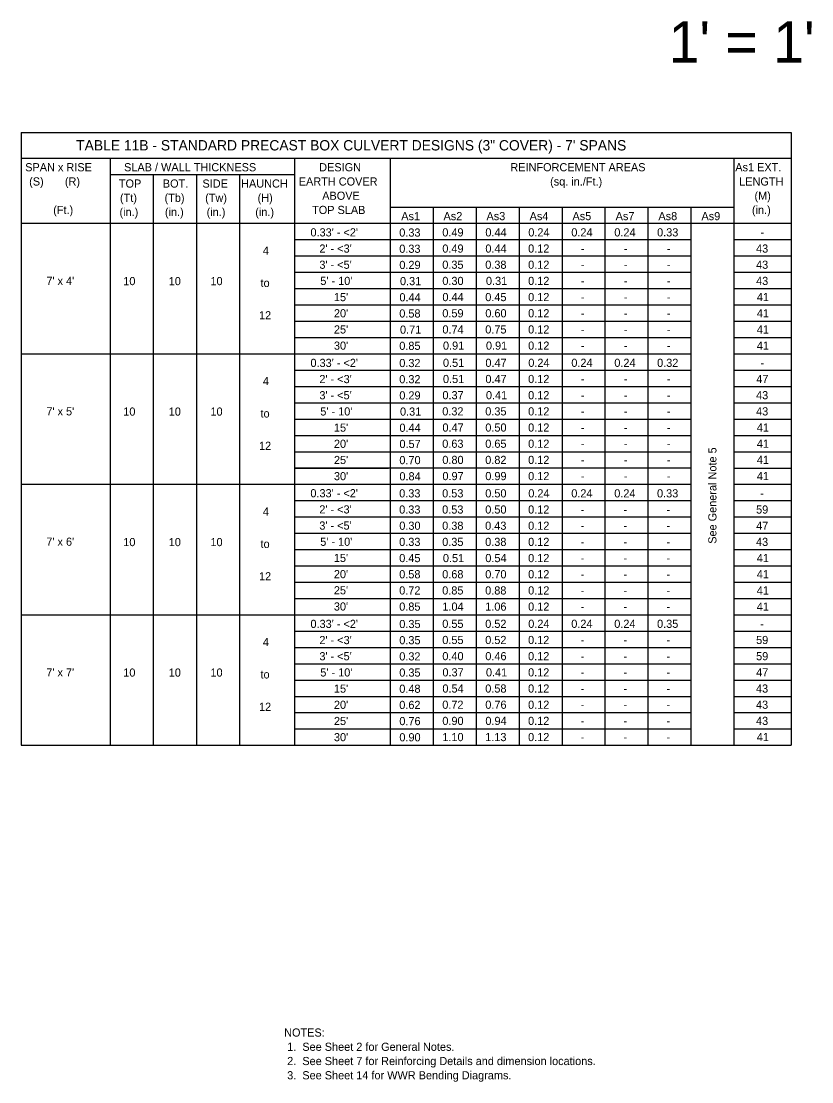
# Model space of a CAD drawing. Extents: x 10342.77 to 10344.98, y 76371.51 to 76372.62.
# Drawn here: x 10343.418 to 10344.028, y 76371.801 to 76372.621 of the extents above; entities that cross this region are included whole.
import ezdxf

# ---------------------------------------------------------------- set-up
doc = ezdxf.new("R2010")
doc.units = 0
doc.layers.add('AdhocPoint_dp', color=7, linetype='Continuous')
doc.layers.add('PlotBorder_dp', color=7, linetype='Continuous')

msp = doc.modelspace()

# ---------------------------------------------------------------- linework, layer by layer
at = {"layer": 'PlotBorder_dp'}
for p, q in [((10343.41763, 76372.53475), (10344.01237, 76372.53475)), ((10343.41763, 76372.53475), (10343.41763, 76372.06133)), ((10344.01237, 76372.53475), (10344.01237, 76372.06133)), ((10343.41763, 76372.51488), (10344.01237, 76372.51488)), ((10343.48627, 76372.51488), (10343.48627, 76372.06133)), ((10343.62871, 76372.51488), (10343.62871, 76372.06133)), ((10343.70259, 76372.51488), (10343.70259, 76372.06133)), ((10343.96818, 76372.51488), (10343.96818, 76372.06133)), ((10343.48627, 76372.50228), (10343.62871, 76372.50228)), ((10343.51963, 76372.50228), (10343.51963, 76372.06133)), ((10343.55299, 76372.50228), (10343.55299, 76372.06133)), ((10343.58635, 76372.50228), (10343.58635, 76372.06133)), ((10343.70259, 76372.47713), (10343.96818, 76372.47713)), ((10343.73579, 76372.47713), (10343.73579, 76372.06133)), ((10343.76899, 76372.47713), (10343.76899, 76372.06133)), ((10343.80219, 76372.47713), (10343.80219, 76372.06133)), ((10343.83539, 76372.47713), (10343.83539, 76372.06133)), ((10343.86858, 76372.47713), (10343.86858, 76372.06133)), ((10343.86858, 76372.47713), (10343.86858, 76372.06133)), ((10343.90178, 76372.47713), (10343.90178, 76372.06133)), ((10343.93498, 76372.47713), (10343.93498, 76372.06133)), ((10343.41763, 76372.46453), (10344.01237, 76372.46453)), ((10343.62871, 76372.45193), (10343.93498, 76372.45193)), ((10343.96818, 76372.45192), (10344.01237, 76372.45192)), ((10343.62871, 76372.43933), (10343.93498, 76372.43933)), ((10343.96818, 76372.43932), (10344.01237, 76372.43932)), ((10343.62871, 76372.42673), (10343.93498, 76372.42673)), ((10343.96818, 76372.42672), (10344.01237, 76372.42672)), ((10343.62871, 76372.41413), (10343.93498, 76372.41413)), ((10343.96818, 76372.41412), (10344.01237, 76372.41412)), ((10343.62871, 76372.40153), (10343.93498, 76372.40153)), ((10343.96818, 76372.40152), (10344.01237, 76372.40152)), ((10343.62871, 76372.38893), (10343.93498, 76372.38893)), ((10343.96818, 76372.38892), (10344.01237, 76372.38892)), ((10343.62871, 76372.37633), (10343.93498, 76372.37633)), ((10343.96818, 76372.37632), (10344.01237, 76372.37632)), ((10343.41763, 76372.36373), (10343.93498, 76372.36373)), ((10343.62931, 76372.36372), (10343.70148, 76372.36372)), ((10343.96818, 76372.36372), (10344.01237, 76372.36372)), ((10343.62871, 76372.35113), (10343.93498, 76372.35113)), ((10343.96818, 76372.35112), (10344.01237, 76372.35112)), ((10343.62871, 76372.33853), (10343.93498, 76372.33853)), ((10343.96818, 76372.33852), (10344.01237, 76372.33852)), ((10343.62871, 76372.32593), (10343.93498, 76372.32593)), ((10343.96818, 76372.32592), (10344.01237, 76372.32592)), ((10343.62871, 76372.31333), (10343.93498, 76372.31333)), ((10343.96818, 76372.31332), (10344.01237, 76372.31332)), ((10343.62871, 76372.30073), (10343.93498, 76372.30073)), ((10343.96818, 76372.30072), (10344.01237, 76372.30072)), ((10343.62871, 76372.28813), (10343.93498, 76372.28813)), ((10343.96818, 76372.28812), (10344.01237, 76372.28812)), ((10343.62871, 76372.27553), (10343.93498, 76372.27553)), ((10343.62931, 76372.27552), (10343.70148, 76372.27552)), ((10343.96818, 76372.27552), (10344.01237, 76372.27552)), ((10343.41763, 76372.26293), (10343.93498, 76372.26293)), ((10343.96818, 76372.26292), (10344.01237, 76372.26292)), ((10343.62871, 76372.25033), (10343.93498, 76372.25033)), ((10343.96818, 76372.25032), (10344.01237, 76372.25032)), ((10343.62871, 76372.23773), (10343.93498, 76372.23773)), ((10343.96818, 76372.23772), (10344.01237, 76372.23772)), ((10343.62871, 76372.22513), (10343.93498, 76372.22513)), ((10343.96818, 76372.22512), (10344.01237, 76372.22512)), ((10343.62871, 76372.21253), (10343.93498, 76372.21253)), ((10343.96818, 76372.21252), (10344.01237, 76372.21252)), ((10343.62871, 76372.19993), (10343.93498, 76372.19993)), ((10343.96818, 76372.19992), (10344.01237, 76372.19992)), ((10343.62871, 76372.18733), (10343.93498, 76372.18733)), ((10343.96818, 76372.18732), (10344.01237, 76372.18732)), ((10343.62871, 76372.17473), (10343.93498, 76372.17473)), ((10343.96818, 76372.17472), (10344.01237, 76372.17472)), ((10343.41763, 76372.16213), (10343.93498, 76372.16213)), ((10343.96818, 76372.16212), (10344.01237, 76372.16212)), ((10343.62871, 76372.14953), (10343.93498, 76372.14953)), ((10343.96818, 76372.14952), (10344.01237, 76372.14952)), ((10343.62871, 76372.13693), (10343.93498, 76372.13693)), ((10343.96818, 76372.13692), (10344.01237, 76372.13692)), ((10343.62871, 76372.12433), (10343.93498, 76372.12433)), ((10343.96818, 76372.12432), (10344.01237, 76372.12432)), ((10343.62871, 76372.11173), (10343.93498, 76372.11173)), ((10343.96818, 76372.11172), (10344.01237, 76372.11172)), ((10343.62871, 76372.09913), (10343.93498, 76372.09913)), ((10343.96818, 76372.09912), (10344.01237, 76372.09912)), ((10343.62871, 76372.08653), (10343.93498, 76372.08653)), ((10343.96818, 76372.08652), (10344.01237, 76372.08652)), ((10343.62871, 76372.07393), (10343.93498, 76372.07393)), ((10343.96818, 76372.07392), (10344.01237, 76372.07392)), ((10343.41763, 76372.06133), (10344.01237, 76372.06133)), ((10343.62931, 76372.06132), (10343.70148, 76372.06132))]:
    msp.add_line(p, q, dxfattribs=at)

# ---------------------------------------------------------------- texts
at = {"layer": 'AdhocPoint_dp'}
for s, height, p in [("1' = 1'", 0.032, (10343.91778, 76372.58867)), ('TABLE 11B - STANDARD PRECAST BOX CULVERT DESIGNS (3" COVER) - 7\' SPANS', 0.008, (10343.46009, 76372.52082)), ('SLAB / WALL THICKNESS', 0.0063, (10343.49709, 76372.50472)), ('As1', 0.0063, (10343.71121, 76372.46696)), ('As2', 0.0063, (10343.74384, 76372.46696)), ('As3', 0.0063, (10343.77704, 76372.46696)), ('As4', 0.0063, (10343.81037, 76372.46696)), ('As5', 0.0063, (10343.84347, 76372.46696)), ('As7', 0.0063, (10343.87681, 76372.46696)), ('As8', 0.0063, (10343.90985, 76372.46696)), ('As9', 0.0063, (10343.9431, 76372.46696)), ('10', 0.0063, (10343.49649, 76372.41675)), ('10', 0.0063, (10343.53159, 76372.41675)), ('10', 0.0063, (10343.56382, 76372.41675)), ('10', 0.0063, (10343.49649, 76372.31597)), ('10', 0.0063, (10343.53159, 76372.31597)), ('10', 0.0063, (10343.56382, 76372.31597)), ('10', 0.0063, (10343.49649, 76372.21514)), ('10', 0.0063, (10343.53159, 76372.21514)), ('10', 0.0063, (10343.56382, 76372.21514)), ('10', 0.0063, (10343.49649, 76372.11436)), ('10', 0.0063, (10343.53159, 76372.11436)), ('10', 0.0063, (10343.56382, 76372.11436))]:
    msp.add_text(s, height=height, dxfattribs=at).set_placement(p)
msp.add_text('See General Note 5', height=0.0063, rotation=90, dxfattribs=at).set_placement((10343.95468, 76372.21699))
at = {"layer": 'PlotBorder_dp'}
for s, p in [('SPAN x RISE', (10343.42072, 76372.50472)), ('DESIGN', (10343.64781, 76372.50472)), ('REINFORCEMENT AREAS', (10343.79549, 76372.50472)), ('(S)       (R)', (10343.42376, 76372.49372)), ('TOP', (10343.49309, 76372.49212)), ('BOT.', (10343.52702, 76372.49212)), ('SIDE', (10343.55762, 76372.49212)), ('HAUNCH', (10343.58751, 76372.49212)), ('EARTH COVER', (10343.63202, 76372.49372)), ('(sq. in./Ft.)', (10343.82619, 76372.49372)), ('ABOVE', (10343.65016, 76372.48272)), ('(Tt)', (10343.49394, 76372.48112)), ('(Tb)', (10343.52836, 76372.48112)), ('(Tw)', (10343.55972, 76372.48112)), ('(H)', (10343.60025, 76372.48112)), ('(Ft.)', (10343.44234, 76372.47172)), ('(in.)', (10343.49355, 76372.47012)), ('(in.)', (10343.52864, 76372.47012)), ('(in.)', (10343.56088, 76372.47012)), ('(in.)', (10343.59844, 76372.47012)), ('TOP SLAB', (10343.64233, 76372.47172)), ("0.33' - <2'", (10343.64107, 76372.45441)), ('0.33', (10343.70966, 76372.45426)), ('0.49', (10343.74293, 76372.45441)), ('0.44', (10343.77619, 76372.45441)), ('0.24', (10343.80935, 76372.45441)), ('0.24', (10343.84258, 76372.45441)), ('0.24', (10343.87579, 76372.45441)), ('0.33', (10343.90884, 76372.45441)), ('-', (10343.98864, 76372.45441)), ("2' - <3'", (10343.64797, 76372.44191)), ('0.33', (10343.70966, 76372.44176)), ('0.49', (10343.74293, 76372.44191)), ('0.44', (10343.77619, 76372.44191)), ('0.12', (10343.80922, 76372.44191)), ('43', (10343.9853, 76372.44191)), ('4', (10343.60429, 76372.44033)), ('-', (10343.84986, 76372.44191)), ('-', (10343.88307, 76372.44191)), ('-', (10343.91625, 76372.44191)), ("3' - <5'", (10343.64797, 76372.42941)), ('0.29', (10343.70973, 76372.42926)), ('0.35', (10343.74289, 76372.42941)), ('0.38', (10343.77609, 76372.42941)), ('0.12', (10343.80922, 76372.42941)), ('-', (10343.84986, 76372.42941)), ('-', (10343.88307, 76372.42941)), ('-', (10343.91625, 76372.42941)), ('43', (10343.9853, 76372.42941)), ("7' x 4'", (10343.43707, 76372.41691)), ("5' - 10'", (10343.64868, 76372.41691)), ('0.31', (10343.71024, 76372.41676)), ('0.30', (10343.74294, 76372.41691)), ('0.31', (10343.77663, 76372.41691)), ('0.12', (10343.80922, 76372.41691)), ('43', (10343.9853, 76372.41691)), ('to', (10343.60251, 76372.41533)), ('-', (10343.84986, 76372.41691)), ('-', (10343.88307, 76372.41691)), ('-', (10343.91625, 76372.41691)), ("15'", (10343.6592, 76372.40441)), ('0.44', (10343.70979, 76372.40426)), ('0.44', (10343.74299, 76372.40441)), ('0.45', (10343.77609, 76372.40441)), ('0.12', (10343.80922, 76372.40441)), ('-', (10343.84986, 76372.40441)), ('-', (10343.88307, 76372.40441)), ('-', (10343.91625, 76372.40441)), ('41', (10343.98587, 76372.40441)), ("20'", (10343.6592, 76372.39191)), ('0.59', (10343.74293, 76372.39191)), ('0.60', (10343.77615, 76372.39191)), ('0.12', (10343.80922, 76372.39191)), ('12', (10343.60134, 76372.39033)), ('0.58', (10343.70969, 76372.39176)), ('-', (10343.84986, 76372.39191)), ('-', (10343.88307, 76372.39191)), ('-', (10343.91625, 76372.39191)), ('41', (10343.98587, 76372.39191)), ("25'", (10343.6592, 76372.37941)), ('0.71', (10343.71024, 76372.37926)), ('0.74', (10343.74299, 76372.37941)), ('0.75', (10343.77609, 76372.37941)), ('0.12', (10343.80922, 76372.37941)), ('-', (10343.84986, 76372.37941)), ('-', (10343.88307, 76372.37941)), ('-', (10343.91625, 76372.37941)), ('41', (10343.98587, 76372.37941)), ("30'", (10343.6592, 76372.36691)), ('0.85', (10343.70969, 76372.36676)), ('0.91', (10343.74343, 76372.36691)), ('0.91', (10343.77663, 76372.36691)), ('0.12', (10343.80922, 76372.36691)), ('-', (10343.84986, 76372.36691)), ('-', (10343.88307, 76372.36691)), ('-', (10343.91625, 76372.36691)), ('41', (10343.98587, 76372.36691)), ("0.33' - <2'", (10343.64107, 76372.35358)), ('0.32', (10343.70967, 76372.35347)), ('0.51', (10343.74343, 76372.35363)), ('0.47', (10343.77621, 76372.35363)), ('0.24', (10343.80935, 76372.35363)), ('0.24', (10343.84258, 76372.35363)), ('0.24', (10343.87579, 76372.35363)), ('0.32', (10343.90885, 76372.35363)), ('-', (10343.98864, 76372.35363)), ('4', (10343.60429, 76372.33953)), ("2' - <3'", (10343.64797, 76372.34108)), ('0.32', (10343.70967, 76372.34097)), ('0.51', (10343.74343, 76372.34113)), ('0.47', (10343.77621, 76372.34113)), ('0.12', (10343.80922, 76372.34113)), ('-', (10343.84986, 76372.34113)), ('-', (10343.88307, 76372.34113)), ('-', (10343.91625, 76372.34113)), ('47', (10343.98545, 76372.34113)), ("3' - <5'", (10343.64797, 76372.32858)), ('0.29', (10343.70973, 76372.32847)), ('0.37', (10343.74301, 76372.32863)), ('0.41', (10343.77663, 76372.32863)), ('0.12', (10343.80922, 76372.32863)), ('43', (10343.9853, 76372.32863)), ('-', (10343.84986, 76372.32863)), ('-', (10343.88307, 76372.32863)), ('-', (10343.91625, 76372.32863)), ("7' x 5'", (10343.43707, 76372.31613)), ('to', (10343.60251, 76372.31453)), ("5' - 10'", (10343.64868, 76372.31608)), ('0.31', (10343.71024, 76372.31597)), ('0.32', (10343.74287, 76372.31613)), ('0.35', (10343.77609, 76372.31613)), ('0.12', (10343.80922, 76372.31613)), ('-', (10343.84986, 76372.31613)), ('-', (10343.88307, 76372.31613)), ('-', (10343.91625, 76372.31613)), ('43', (10343.9853, 76372.31613)), ("15'", (10343.6592, 76372.30358)), ('0.44', (10343.70979, 76372.30347)), ('0.47', (10343.74301, 76372.30363)), ('0.50', (10343.77615, 76372.30363)), ('0.12', (10343.80922, 76372.30363)), ('41', (10343.98587, 76372.30363)), ('-', (10343.84986, 76372.30363)), ('-', (10343.88307, 76372.30363)), ('-', (10343.91625, 76372.30363)), ('12', (10343.60134, 76372.28953)), ("20'", (10343.6592, 76372.29108)), ('0.57', (10343.70981, 76372.29097)), ('0.63', (10343.74286, 76372.29113)), ('0.65', (10343.77609, 76372.29113)), ('0.12', (10343.80922, 76372.29113)), ('-', (10343.84986, 76372.29113)), ('-', (10343.88307, 76372.29113)), ('-', (10343.91625, 76372.29113)), ('41', (10343.98587, 76372.29113)), ("25'", (10343.6592, 76372.27858)), ('0.70', (10343.70975, 76372.27847)), ('0.80', (10343.74294, 76372.27863)), ('0.82', (10343.77607, 76372.27863)), ('0.12', (10343.80922, 76372.27863)), ('41', (10343.98587, 76372.27863)), ('-', (10343.84986, 76372.27863)), ('-', (10343.88307, 76372.27863)), ('-', (10343.91625, 76372.27863)), ("30'", (10343.6592, 76372.26608)), ('0.84', (10343.70979, 76372.26597)), ('0.97', (10343.74301, 76372.26613)), ('0.99', (10343.77613, 76372.26613)), ('0.12', (10343.80922, 76372.26613)), ('-', (10343.84986, 76372.26613)), ('-', (10343.88307, 76372.26613)), ('-', (10343.91625, 76372.26613)), ('41', (10343.98587, 76372.26613)), ("0.33' - <2'", (10343.64102, 76372.2529)), ('0.33', (10343.70961, 76372.2528)), ('0.53', (10343.74281, 76372.2528)), ('0.50', (10343.77609, 76372.2528)), ('0.24', (10343.80935, 76372.2528)), ('0.24', (10343.84253, 76372.2528)), ('0.24', (10343.87574, 76372.2528)), ('0.33', (10343.90879, 76372.2528)), ('-', (10343.98858, 76372.2528)), ('4', (10343.60429, 76372.23873)), ("2' - <3'", (10343.64791, 76372.2404)), ('0.33', (10343.70961, 76372.2403)), ('0.53', (10343.74281, 76372.2403)), ('0.50', (10343.77609, 76372.2403)), ('0.12', (10343.80922, 76372.2403)), ('-', (10343.84981, 76372.2403)), ('-', (10343.88302, 76372.2403)), ('-', (10343.9162, 76372.2403)), ('59', (10343.98532, 76372.2403)), ("3' - <5'", (10343.64791, 76372.2279)), ('0.30', (10343.70969, 76372.2278)), ('0.38', (10343.74283, 76372.2278)), ('0.43', (10343.77601, 76372.2278)), ('0.12', (10343.80922, 76372.2278)), ('-', (10343.84981, 76372.2278)), ('-', (10343.88302, 76372.2278)), ('-', (10343.9162, 76372.2278)), ('47', (10343.98539, 76372.2278)), ("7' x 6'", (10343.43702, 76372.21545)), ('to', (10343.60251, 76372.21373)), ("5' - 10'", (10343.64863, 76372.2154)), ('0.33', (10343.70961, 76372.2153)), ('0.35', (10343.74284, 76372.2153)), ('0.38', (10343.77603, 76372.2153)), ('0.12', (10343.80922, 76372.2153)), ('-', (10343.84981, 76372.2153)), ('-', (10343.88302, 76372.2153)), ('-', (10343.9162, 76372.2153)), ('43', (10343.98525, 76372.2153)), ("15'", (10343.65915, 76372.2029)), ('0.45', (10343.70964, 76372.2028)), ('0.51', (10343.74338, 76372.2028)), ('0.54', (10343.77614, 76372.2028)), ('0.12', (10343.80922, 76372.2028)), ('-', (10343.84981, 76372.2028)), ('-', (10343.88302, 76372.2028)), ('-', (10343.9162, 76372.2028)), ('41', (10343.98582, 76372.2028)), ('12', (10343.60134, 76372.18873)), ("20'", (10343.65915, 76372.1904)), ('0.58', (10343.70963, 76372.1903)), ('0.68', (10343.74283, 76372.1903)), ('0.70', (10343.77609, 76372.1903)), ('0.12', (10343.80922, 76372.1903)), ('41', (10343.98582, 76372.1903)), ('-', (10343.84981, 76372.1903)), ('-', (10343.88302, 76372.1903)), ('-', (10343.9162, 76372.1903)), ("25'", (10343.65915, 76372.1779)), ('0.72', (10343.70962, 76372.1778)), ('0.85', (10343.74284, 76372.1778)), ('0.88', (10343.77603, 76372.1778)), ('0.12', (10343.80922, 76372.1778)), ('-', (10343.84981, 76372.1778)), ('-', (10343.88302, 76372.1778)), ('-', (10343.9162, 76372.1778)), ('41', (10343.98582, 76372.1778)), ("30'", (10343.65915, 76372.1654)), ('0.85', (10343.70964, 76372.1653)), ('1.04', (10343.74294, 76372.1653)), ('1.06', (10343.77608, 76372.1653)), ('0.12', (10343.80922, 76372.1653)), ('41', (10343.98582, 76372.1653)), ('-', (10343.84981, 76372.1653)), ('-', (10343.88302, 76372.1653)), ('-', (10343.9162, 76372.1653)), ("0.33' - <2'", (10343.64107, 76372.15196)), ('0.35', (10343.70969, 76372.15186)), ('0.55', (10343.74289, 76372.15202)), ('0.52', (10343.77607, 76372.15202)), ('0.24', (10343.8093, 76372.15202)), ('0.24', (10343.84253, 76372.15202)), ('0.24', (10343.87574, 76372.15202)), ('0.35', (10343.90882, 76372.15202)), ('-', (10343.98858, 76372.15202)), ("2' - <3'", (10343.64797, 76372.13946)), ('0.35', (10343.70969, 76372.13936)), ('0.55', (10343.74289, 76372.13952)), ('0.52', (10343.77607, 76372.13952)), ('0.12', (10343.80917, 76372.13952)), ('59', (10343.98532, 76372.13952)), ('4', (10343.60429, 76372.13793)), ('-', (10343.84981, 76372.13952)), ('-', (10343.88302, 76372.13952)), ('-', (10343.9162, 76372.13952)), ("3' - <5'", (10343.64797, 76372.12696)), ('0.32', (10343.70967, 76372.12686)), ('0.40', (10343.74294, 76372.12702)), ('0.46', (10343.77613, 76372.12702)), ('0.12', (10343.80917, 76372.12702)), ('-', (10343.84981, 76372.12702)), ('-', (10343.88302, 76372.12702)), ('-', (10343.9162, 76372.12702)), ('59', (10343.98532, 76372.12702)), ("7' x 7'", (10343.43702, 76372.11446)), ("5' - 10'", (10343.64868, 76372.11446)), ('0.35', (10343.70969, 76372.11436)), ('0.37', (10343.74301, 76372.11452)), ('0.41', (10343.77663, 76372.11452)), ('0.12', (10343.80917, 76372.11452)), ('47', (10343.98539, 76372.11452)), ('to', (10343.60251, 76372.11293)), ('-', (10343.84981, 76372.11452)), ('-', (10343.88302, 76372.11452)), ('-', (10343.9162, 76372.11452)), ("15'", (10343.6592, 76372.10196)), ('0.48', (10343.70969, 76372.10186)), ('0.54', (10343.74299, 76372.10202)), ('0.58', (10343.77609, 76372.10202)), ('0.12', (10343.80917, 76372.10202)), ('-', (10343.84981, 76372.10202)), ('-', (10343.88302, 76372.10202)), ('-', (10343.9162, 76372.10202)), ('43', (10343.98525, 76372.10202)), ("20'", (10343.6592, 76372.08946)), ('0.62', (10343.70967, 76372.08936)), ('0.72', (10343.74287, 76372.08952)), ('0.76', (10343.77613, 76372.08952)), ('0.12', (10343.80917, 76372.08952)), ('43', (10343.98525, 76372.08952)), ('12', (10343.60134, 76372.08793)), ('-', (10343.84981, 76372.08952)), ('-', (10343.88302, 76372.08952)), ('-', (10343.9162, 76372.08952)), ("25'", (10343.6592, 76372.07696)), ('0.76', (10343.70973, 76372.07686)), ('0.90', (10343.74294, 76372.07702)), ('0.94', (10343.77619, 76372.07702)), ('0.12', (10343.80917, 76372.07702)), ('-', (10343.84981, 76372.07702)), ('-', (10343.88302, 76372.07702)), ('-', (10343.9162, 76372.07702)), ('43', (10343.98525, 76372.07702)), ("30'", (10343.6592, 76372.06446)), ('0.90', (10343.70975, 76372.06436)), ('1.10', (10343.74294, 76372.06452)), ('1.13', (10343.77606, 76372.06452)), ('0.12', (10343.80917, 76372.06452)), ('41', (10343.98582, 76372.06452)), ('-', (10343.84981, 76372.06452)), ('-', (10343.88302, 76372.06452)), ('-', (10343.9162, 76372.06452)), ('NOTES:', (10343.62073, 76371.83627)), (' 1.  See Sheet 2 for General Notes.', (10343.62073, 76371.82527)), (' 2.  See Sheet 7 for Reinforcing Details and dimension locations.', (10343.62073, 76371.81427)), (' 3.  See Sheet 14 for WWR Bending Diagrams.', (10343.62073, 76371.80327))]:
    msp.add_text(s, height=0.0063, dxfattribs=at).set_placement(p)
for s, p in [('As1 EXT.', (10343.96923, 76372.50472)), ('LENGTH', (10343.97225, 76372.49372)), ('(M)', (10343.98406, 76372.48272)), ('(in.)', (10343.9821, 76372.47172))]:
    msp.add_text(s, height=0.0063, rotation=360, dxfattribs=at).set_placement(p)

doc.saveas('drawing.dxf')
